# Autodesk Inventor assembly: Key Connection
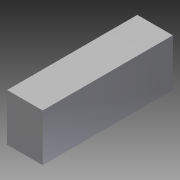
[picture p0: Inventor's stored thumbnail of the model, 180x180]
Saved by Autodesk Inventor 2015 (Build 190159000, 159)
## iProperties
Created: 2007-02
Part Number: Key Connection
Document SubType Name: Assembly
Designer: Autodesk, Inc.
Mass: 33.2068 g
Surface Area: 17.9435 cm^2
Volume: 4.22479 cm^3
Density: 7.86 g/cm^3
ClientObjectVersion: 1
Author: Autodesk, Inc.
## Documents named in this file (2)
- C:\Users\Public\Documents\Autodesk\Inventor 2015\Samples\Models\Assemblies\Blower\Blower\Design Accelerator\Key Connection2.iam
- C:\Users\Public\Documents\Autodesk\Inventor 2015\Samples\Standard Parts\en-US\USAS B17.1(1)\USAS B17.1 - 1_2 x 3_8 x 1 3_8.ipt
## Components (1 placed, 1 different names)
1. USAS B17.1 - 1/2 x 3/8 x 1 3/8:1
